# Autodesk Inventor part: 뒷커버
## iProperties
Company: 한국ATC센터
Created: 2014-08
Part Number: 뒷커버
Document SubType Name: Modeling
Designer: KYOUNG IL JANG
Density: 2.71 g/cm^3
Material: 알루미늄-6061
Mass: 260.103 g
Surface Area: 228.85 cm^2
Volume: 95.9791 cm^3
Author: KYOUNG IL JANG
